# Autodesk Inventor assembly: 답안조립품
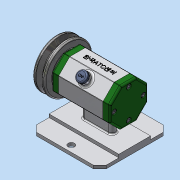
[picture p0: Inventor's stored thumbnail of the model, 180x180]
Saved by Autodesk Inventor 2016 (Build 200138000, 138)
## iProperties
Created: 2018-06
Part Number: 답안조립품
Material: 일반
Document SubType Name: Assembly
Designer: Administrator
Author: Administrator
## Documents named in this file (16)
- C:\Users\Administrator\Desktop\480607V1011\답안조립품.iam
- C:\Users\Administrator\Desktop\480607V1011\본체.ipt
- C:\Users\Administrator\Desktop\480607V1011\베어링 15x32x9.ipt
- C:\Users\Administrator\Desktop\480607V1011\축.ipt
- C:\Users\Administrator\Desktop\480607V1011\키 3x3x12.ipt
- 키 3x3x12.ipt
- C:\Users\Administrator\Desktop\480607V1011\뒤커버.ipt
- C:\Users\Administrator\Desktop\480607V1011\앞커버.ipt
- C:\Users\Administrator\Desktop\480607V1011\오일 실 15 25 7.ipt
- C:\Users\Administrator\Desktop\480607V1011\V벨트풀리.ipt
- C:\Users\Administrator\Desktop\480607V1011\와셔 8x17.ipt
- C:\Users\Administrator\Desktop\480607V1011\스프링와셔 8.ipt
- C:\Users\Administrator\Desktop\480607V1011\너트 M8.ipt
- 너트 M8.ipt
- C:\Users\Administrator\Desktop\480607V1011\고무캡.ipt
- C:\Users\Administrator\Desktop\480607V1011\볼트 M4x12.ipt
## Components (2 placed, 2 different names)
1. V벨트풀리:1
2. 고무캡:1
